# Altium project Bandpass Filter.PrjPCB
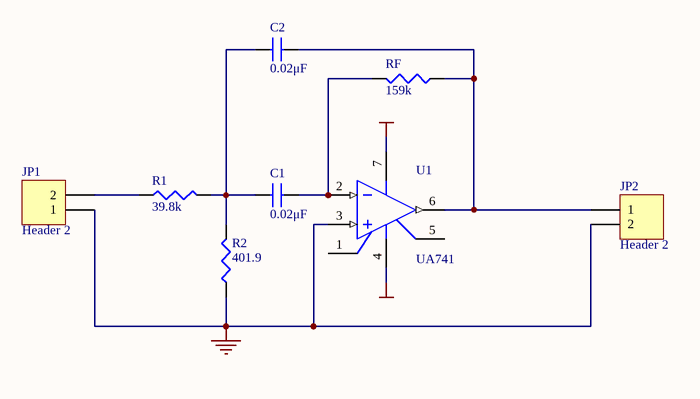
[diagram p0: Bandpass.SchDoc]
1 sheet, 8 parts. Net scope: global (net labels, ports and power ports of the same name join across sheets).
Board file: PCB.PcbDoc

## Sheet Bandpass.SchDoc
size B

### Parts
C1  0.02μF  [RAD-0.1]
C2  0.02μF  [RAD-0.1]
JP1  Header 2  [HDR1X2]
JP2  Header 2  [HDR1X2]
R1  39.8k  [AXIAL-0.3]
R2  401.9  [AXIAL-0.3]
RF  159k  [AXIAL-0.3]
U1  UA741  [DIP-8]

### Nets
+15V: U1.7(V+)
-15V: U1.4(V-)
GND: JP1.1 JP2.2 R2.2(BOT) U1.3(+IN)
NetC1_1: C1.1 C2.1 R1.1(TOP) R2.1(TOP)
NetC1_2: C1.2 RF.1(TOP) U1.2(-IN)
NetC2_2: C2.2 JP2.1 RF.2(BOT) U1.6(OUT)
NetJP1_2: JP1.2 R1.2(BOT)

Not connected (* = marked no-connect by the designer): U1 1(OFFSET_NULL_1) 5(OFFSET_NULL_2)

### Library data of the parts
C1 C2 = CAP: Capacitor
JP1 JP2 = Header 2: Header, 2-Pin; Manufacturer: Generic Components; Class I: Connector
R1 R2 RF = RES: Resistor
U1 = UA741: General-Purpose Operational Amplifier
